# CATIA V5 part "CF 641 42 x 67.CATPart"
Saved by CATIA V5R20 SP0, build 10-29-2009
Part number: CF 641 42 x 67
Definition: NONE
Nomenclature: CF 641 42 x 67
Source: Unknown
Description: CF 641 42 x 67
Bounding box of the stored display mesh (mm): x -37 to 30, y -31.5 to 31.5, z -31.5 to 31.5
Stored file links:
  C:\Users\Utente\Desktop\IO LAVORO\3D X SITO CF\X SITO\CF 641\CF 641 42 x 67.CATPart
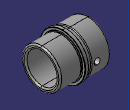
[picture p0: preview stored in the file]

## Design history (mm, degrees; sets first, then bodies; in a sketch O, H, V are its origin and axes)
Body1 "CF 641 42 x 67" (main body)
  Solid1: solid without history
